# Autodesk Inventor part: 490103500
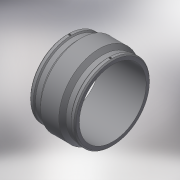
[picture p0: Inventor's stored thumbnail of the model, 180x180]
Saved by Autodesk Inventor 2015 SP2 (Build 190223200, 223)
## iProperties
Created: 2017-06
Part Number: 490103500
Material: Generic
Description: PLASSON COUPLER 500
Document SubType Name: Modeling
Designer: KIM
Mass: 22528.3 g
Surface Area: 12982.6 cm^2
Volume: 22528.3 cm^3
Density: 1 g/cm^3
Appearance: Default
Author: KIM
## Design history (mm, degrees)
derived "490103.ipt"
feature "Solid1::490103.ipt"
tag "TaggingFeature1"
body "Solid1"
other parameters: "d22" = 566, "d23" = 603, "d24" = 549.02, "d25" = 135 deg, "d26" = 136, "d27" = 135 deg, "d29" = 283, "d35" = 15, "d39" = 0, "d40" = 4, "d41" = 14, "d42" = 0, "d43" = 135 deg, "d44" = 37.4, "d46" = 6, "d47" = 0, "D_" = 603, "A_" = 283, "d_2" = 12
